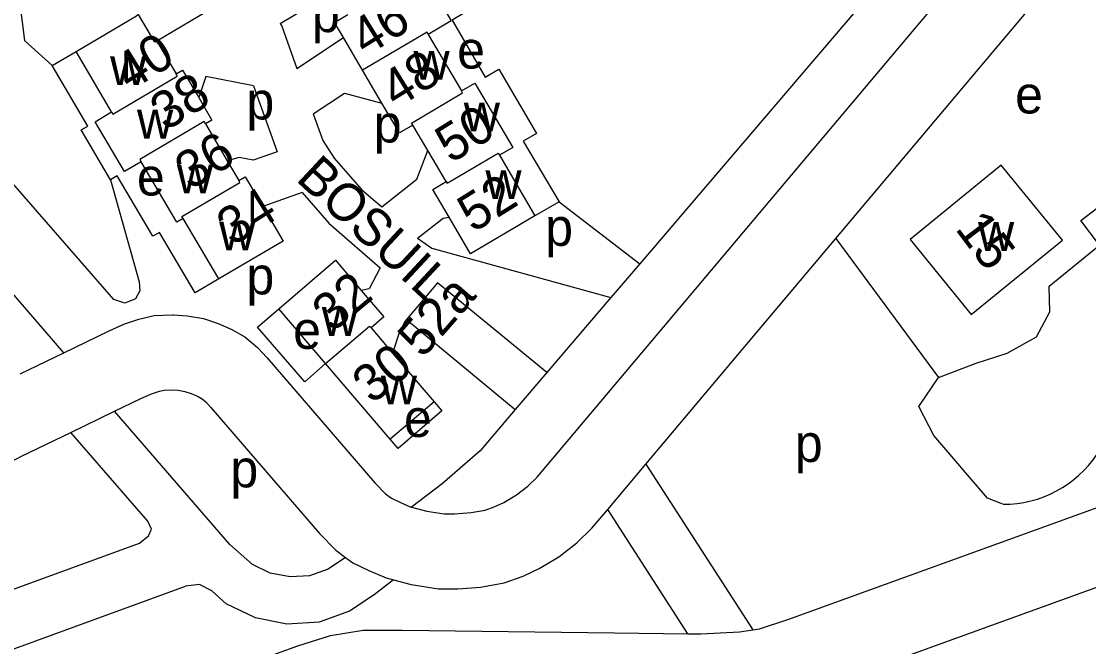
# Model space of a CAD drawing. Extents: x 155854 to 157362, y 383621 to 384685.
# Drawn here: x 156920.8 to 157034.9, y 383747.7 to 383814.5 of the extents above; entities that cross this region are included whole.
import ezdxf

# ---------------------------------------------------------------- set-up
doc = ezdxf.new("R2010")
doc.units = 0
for name, color, linetype in [('BLT_Basislijn', 7, 'Continuous'), ('BLT_Bebouwing', 7, 'Continuous'), ('BLT_Centroide', 7, 'Continuous'), ('BLT_Huisnummer', 7, 'Continuous'), ('BLT_Huisnummer_zonder_bebouwing', 7, 'Continuous'), ('BLT_Onderverdeling_panden', 7, 'Continuous'), ('BLT_Straatnaam_verkleind', 7, 'Continuous')]:
    doc.layers.add(name, color=color, linetype=linetype)

msp = doc.modelspace()

# ---------------------------------------------------------------- linework, layer by layer
at = {"layer": 'BLT_Basislijn'}
for p, q in [((157007.86, 383791.26), (157050.45, 383841.83)), ((156925.36, 383779.07), (156890.83, 383818.91)), ((157012.64, 383818.7), (156986.9, 383788.56)), ((156948.49, 383814.23), (156954.24, 383817.68)), ((156950.27, 383809.42), (156955.23, 383812.74)), ((156924.11, 383809.75), (156926.66, 383811.25)), ((156945.62, 383807.57), (156948.14, 383800.53)), ((156950.82, 383796.18), (156946.63, 383794.67)), ((156978.28, 383795.2), (156975.71, 383793.68)), ((156978.28, 383795.2), (156986.9, 383788.56)), ((156997.4, 383778.85), (157007.86, 383791.26)), ((157007.86, 383791.26), (157018.83, 383776.42)), ((156986.9, 383788.56), (156983.81, 383784.96)), ((156964.15, 383785.19), (156961.99, 383782.61)), ((156983.81, 383784.96), (156976.97, 383776.94)), ((156961.99, 383782.61), (156973.6, 383773)), ((156920.69, 383776.82), (156925.36, 383779.07)), ((156987.55, 383767.15), (156997.4, 383778.85)), ((156976.97, 383776.94), (156973.6, 383773)), ((156926.12, 383770.56), (156930.78, 383772.81)), ((156934.34, 383761.07), (156926.12, 383770.56)), ((156983.48, 383762.32), (156987.55, 383767.15)), ((156987.55, 383767.15), (156998.98, 383749.48)), ((156992.06, 383749.05), (156983.48, 383762.32)), ((156955.47, 383757.2), (156956.23, 383756.63)), ((156786.01, 383698.59), (156938.36, 383754.12)), ((156984.19, 383749.15), (156992.06, 383749.05))]:
    msp.add_line(p, q, dxfattribs=at)
for points in [[(156962.53, 383762.57), (156964.14, 383762.14), (156966.02, 383761.85), (156967.12, 383761.85), (156968.88, 383761.99), (156970.37, 383762.24), (156971.36, 383762.6), (156972.39, 383763.09), (156973.75, 383763.9), (156974.95, 383764.82), (156975.94, 383765.78), (157039.24, 383840.94)], [(156961.33, 383827.21), (156965.14, 383820.76), (156966.16, 383821.36), (156969.31, 383816.03), (156966.86, 383814.59), (156970.38, 383808.5), (156971.84, 383809.34), (156975.88, 383802.49), (156974.46, 383801.66), (156978.28, 383795.2)], [(156930.33, 383797.53), (156933.42, 383786.63), (156933.49, 383785.67), (156933.02, 383784.82), (156931.88, 383784.36), (156930.72, 383784.77), (156898.3, 383821.94)], [(156929.31, 383821.54), (156927.43, 383821.08), (156924.6, 383820.45), (156921.87, 383818.62), (156920.58, 383816.92), (156921.16, 383812.41), (156924.11, 383809.75)], [(156948.49, 383814.23), (156948.66, 383813.94), (156950.27, 383809.42)], [(156930.33, 383797.53), (156927.2, 383802.86), (156927.92, 383803.28), (156924.11, 383809.75)], [(156945.62, 383807.57), (156940.55, 383808.57), (156939.77, 383806.32)], [(156952.01, 383804.57), (156955.35, 383806.8), (156959.35, 383805.73)], [(156952.01, 383804.57), (156953.02, 383801.74), (156954.26, 383799.84), (156957.22, 383796.47), (156959.33, 383794.64)], [(156948.14, 383800.53), (156945.6, 383799.62), (156944.11, 383799.92), (156942.81, 383799.57)], [(156959.33, 383794.64), (156963.09, 383797.6), (156964.25, 383800.66)], [(156941.92, 383786.95), (156939.38, 383785.45), (156935.58, 383791.91), (156934.87, 383791.5), (156931.06, 383797.97), (156930.33, 383797.53)], [(156950.82, 383796.18), (156953.69, 383792.92), (156959.18, 383788.15)], [(157018.83, 383776.42), (157022.85, 383777.97), (157026.16, 383779.03), (157029.3, 383780.78), (157030.74, 383783.44), (157030.65, 383786.17), (157036.03, 383790.55), (157034.03, 383793.18), (157035.86, 383794.57)], [(156963.17, 383791.3), (156965.9, 383793.44), (156966.52, 383793.55)], [(156963.17, 383791.3), (156963.27, 383791.22), (156964.67, 383790.24), (156983.81, 383784.96)], [(156959.18, 383788.15), (156957.99, 383785.88), (156957.14, 383785.72)], [(156976.97, 383776.94), (156965.28, 383786.54), (156964.15, 383785.19)], [(156925.36, 383779.07), (156930.22, 383781.42), (156931.77, 383782.11), (156933.38, 383782.67), (156935.03, 383783.05), (156936.96, 383783.12), (156937.09, 383783.11)], [(156937.09, 383783.11), (156938.54, 383783.02), (156940.3, 383782.71), (156941.86, 383782.18), (156943.3, 383781.55), (156944.69, 383780.76), (156946.05, 383779.64), (156947.05, 383778.55), (156958.58, 383765.18), (156959.72, 383764.01), (156960.38, 383763.52), (156961.26, 383763.1), (156962.43, 383762.59), (156962.53, 383762.57)], [(156953.33, 383777.9), (156951.11, 383775.97), (156946.06, 383781.8), (156948.32, 383783.76)], [(156961.99, 383782.61), (156961.81, 383782.39), (156961.19, 383781.21), (156960.49, 383779.03)], [(157025.72, 383762.88), (157024.08, 383763.54), (157018.32, 383770.23), (157016.74, 383773.33), (157018.83, 383776.42)], [(156930.78, 383772.81), (156933.6, 383774.17), (156934.73, 383774.67), (156935.58, 383774.97), (156936.07, 383775.08), (156936.87, 383775.11), (156937.59, 383775.07), (156938.3, 383774.94), (156938.97, 383774.71), (156939.72, 383774.38), (156940.14, 383774.14), (156940.53, 383773.82), (156941.08, 383773.23), (156952.68, 383759.77), (156954.43, 383757.98), (156955.47, 383757.2)], [(156964.93, 383773.84), (156965.77, 383772.86), (156961.08, 383768.84), (156960.24, 383769.83)], [(156955.47, 383757.2), (156953.62, 383755.97), (156951.63, 383755.24), (156949.53, 383755.12), (156947.42, 383755.52), (156945.53, 383756.45), (156943.1, 383758.6), (156930.78, 383772.81)], [(156973.6, 383773), (156969.85, 383768.6), (156965.78, 383765.05), (156962.53, 383762.57)], [(156918.35, 383766.84), (156919.78, 383767.46), (156920.85, 383768.01), (156926.12, 383770.56)], [(156980.18, 383758.75), (156981.8, 383760.33), (156983.48, 383762.32)], [(156998.98, 383749.48), (156999.7, 383749.59), (157002.83, 383750.63), (157037.57, 383763.18)], [(156797.74, 383709.25), (156933.44, 383758.72), (156934.4, 383759.51), (156934.72, 383760.23), (156934.34, 383761.07)], [(156960.6, 383754.8), (156962.48, 383754.3), (156965.4, 383753.85), (156967.45, 383753.85), (156969.88, 383754.04), (156972.42, 383754.48), (156974.45, 383755.21), (156976.17, 383756.03), (156978.24, 383757.27), (156980.18, 383758.75)], [(156797.17, 383684.24), (156799.67, 383684.9), (156952.91, 383740.18), (156955.72, 383741.07), (156957.99, 383741.45), (156961.48, 383741.45), (156993.6, 383741.03), (156998.38, 383741.29), (157001.59, 383741.78), (157005.45, 383743.07), (157045.31, 383757.47)], [(156956.23, 383756.63), (156957.96, 383755.81), (156959.8, 383755.02), (156960.6, 383754.8)], [(156960.6, 383754.8), (156958.53, 383753.22), (156955.89, 383751.47), (156952.65, 383750.29), (156949.19, 383750.09), (156945.83, 383750.74), (156942.72, 383752.26), (156941.16, 383753.64), (156939.85, 383754.32), (156938.36, 383754.12)], [(156786.01, 383698.59), (156787.59, 383695.9), (156789, 383694.15), (156790.22, 383693.14), (156791.43, 383692.48), (156792.49, 383692.09), (156794.05, 383691.91), (156795.22, 383692), (156797.29, 383692.54), (156950.35, 383747.76), (156953.85, 383748.87)], [(156953.85, 383748.87), (156957.33, 383749.45), (156961.53, 383749.45), (156984.19, 383749.15)], [(156992.06, 383749.05), (156993.43, 383749.04), (156997.56, 383749.26), (156998.98, 383749.48)]]:
    msp.add_lwpolyline(points, dxfattribs=at)
msp.add_arc((157025.75, 383774.95), 12.07, 269.8891, 326.2914, dxfattribs=at)
at = {"layer": 'BLT_Bebouwing'}
for p, q in [((156941.68, 383816.1), (156935.29, 383812.34)), ((156926.66, 383811.25), (156933.12, 383815.06)), ((156957.29, 383809.24), (156955.23, 383812.74)), ((156964.3, 383813.07), (156967.85, 383807.02)), ((156935.29, 383812.34), (156937.35, 383808.85)), ((156930.47, 383804.78), (156926.66, 383811.25)), ((156959.35, 383805.73), (156957.29, 383809.24)), ((156940.49, 383803.5), (156942.81, 383799.57)), ((156964.25, 383800.66), (156962.65, 383803.37)), ((156966.21, 383797.34), (156964.25, 383800.66)), ((156971.91, 383800.15), (156975.71, 383793.68)), ((156942.81, 383799.57), (156944.06, 383797.46)), ((156946.63, 383794.67), (156948.8, 383790.99)), ((156941.92, 383786.95), (156938.1, 383793.4)), ((156968.83, 383789.64), (156966.52, 383793.55)), ((156975.71, 383793.68), (156968.83, 383789.64)), ((156948.8, 383790.99), (156941.92, 383786.95)), ((156953.33, 383777.9), (156948.32, 383783.76)), ((156958.19, 383781.72), (156960.49, 383779.03)), ((156960.49, 383779.03), (156964.93, 383773.84)), ((156960.24, 383769.83), (156953.33, 383777.9)), ((156964.93, 383773.84), (156960.24, 383769.83))]:
    msp.add_line(p, q, dxfattribs=at)
for points in [[(156962.58, 383819.24), (156963.61, 383819.85), (156966.75, 383814.52), (156964.3, 383813.07)], [(156955.23, 383812.74), (156954.28, 383814.34), (156955.71, 383815.18)], [(156937.35, 383808.85), (156938.04, 383809.26), (156939.77, 383806.32)], [(156967.85, 383807.02), (156969.28, 383807.86), (156973.33, 383800.99), (156971.91, 383800.15)], [(156939.77, 383806.32), (156941.19, 383803.91), (156940.49, 383803.5)], [(156962.65, 383803.37), (156961.23, 383802.54), (156959.35, 383805.73)], [(156933.61, 383799.46), (156931.84, 383798.42), (156928.71, 383803.74), (156930.47, 383804.78)], [(156938.1, 383793.4), (156937.42, 383793), (156933.61, 383799.46)], [(156944.06, 383797.46), (156944.74, 383797.87), (156946.63, 383794.67)], [(156966.52, 383793.55), (156964.78, 383796.5), (156966.21, 383797.34)], [(156948.32, 383783.76), (156954.39, 383788.95), (156957.14, 383785.72)], [(156957.14, 383785.72), (156959.56, 383782.89), (156958.19, 383781.72)]]:
    msp.add_lwpolyline(points, dxfattribs=at)
msp.add_lwpolyline([(157025.54, 383799.11), (157015.79, 383791.17), (157022.33, 383783.15), (157032.09, 383791.1)], close=True, dxfattribs=at)
at = {"layer": 'BLT_Onderverdeling_panden'}
for points in [[(156935.29, 383812.34), (156935.09, 383812.23), (156933.35, 383815.19), (156933.12, 383815.06)], [(156964.3, 383813.07), (156964.18, 383813.29), (156957.29, 383809.24)], [(156930.47, 383804.78), (156930.59, 383804.56), (156937.48, 383808.62), (156937.35, 383808.85)], [(156962.65, 383803.37), (156962.52, 383803.6), (156967.98, 383806.81), (156967.85, 383807.02)], [(156940.49, 383803.5), (156940.35, 383803.75), (156933.47, 383799.7), (156933.61, 383799.46)], [(156966.21, 383797.34), (156966.31, 383797.16), (156971.78, 383800.38), (156971.91, 383800.15)], [(156938.1, 383793.4), (156937.98, 383793.6), (156944.18, 383797.26), (156944.06, 383797.46)], [(156953.33, 383777.9), (156958.03, 383781.91), (156958.19, 383781.72)]]:
    msp.add_lwpolyline(points, dxfattribs=at)

# ---------------------------------------------------------------- texts
at = {"layer": 'BLT_Centroide'}
for s, p in [('p', (156951.87, 383813.31)), ('e', (156967.39, 383809.41)), ('w', (156962.72, 383808.23)), ('w', (156930.3, 383807.66)), ('p', (156944.87, 383803.98)), ('e', (157027.02, 383804.62)), ('w', (156968.1, 383802.71)), ('w', (156933.18, 383801.94)), ('p', (156958.48, 383801.52)), ('e', (156933.17, 383795.86)), ('w', (156937.44, 383796.09)), ('w', (156970.41, 383795.49)), ('w', (156941.96, 383789.99)), ('p', (156976.8, 383790.48)), ('w', (157023.05, 383789.95)), ('p', (156944.87, 383785.3)), ('w', (156952.93, 383780.87)), ('e', (156949.87, 383779.48)), ('w', (156959.24, 383773.55)), ('e', (156961.71, 383770.07)), ('p', (157003.48, 383767.4)), ('p', (156943.16, 383764.69))]:
    msp.add_text(s, height=4, dxfattribs=at).set_placement(p)
at = {"layer": 'BLT_Huisnummer'}
for s, rotation, p in [('46', 31.9241, (156957.62, 383810.64)), ('40', 31.9241, (156932.42, 383806.93)), ('48', 31.9241, (156960.88, 383805.08)), ('38', 31.9241, (156936.25, 383802.68)), ('50', 31.9241, (156966.71, 383799.22)), ('36', 31.9241, (156938.9, 383796.36)), ('52', 31.9241, (156969.09, 383791.82)), ('34', 31.9241, (156943.37, 383790.38)), ('15', 306.9241, (157020.53, 383792.31)), ('32', 39.9241, (156954.05, 383781.13)), ('30', 39.9241, (156958.33, 383773.49))]:
    msp.add_text(s, height=4, rotation=rotation, dxfattribs=at).set_placement(p)
at = {"layer": 'BLT_Huisnummer_zonder_bebouwing'}
msp.add_text('52a', height=4, rotation=48.9241, dxfattribs=at).set_placement((156963.71, 383778.37))
at = {"layer": 'BLT_Straatnaam_verkleind'}
msp.add_text('BOSUIL', height=4, rotation=317.0275, dxfattribs=at).set_placement((156950.04, 383797.53))

doc.saveas('drawing.dxf')
